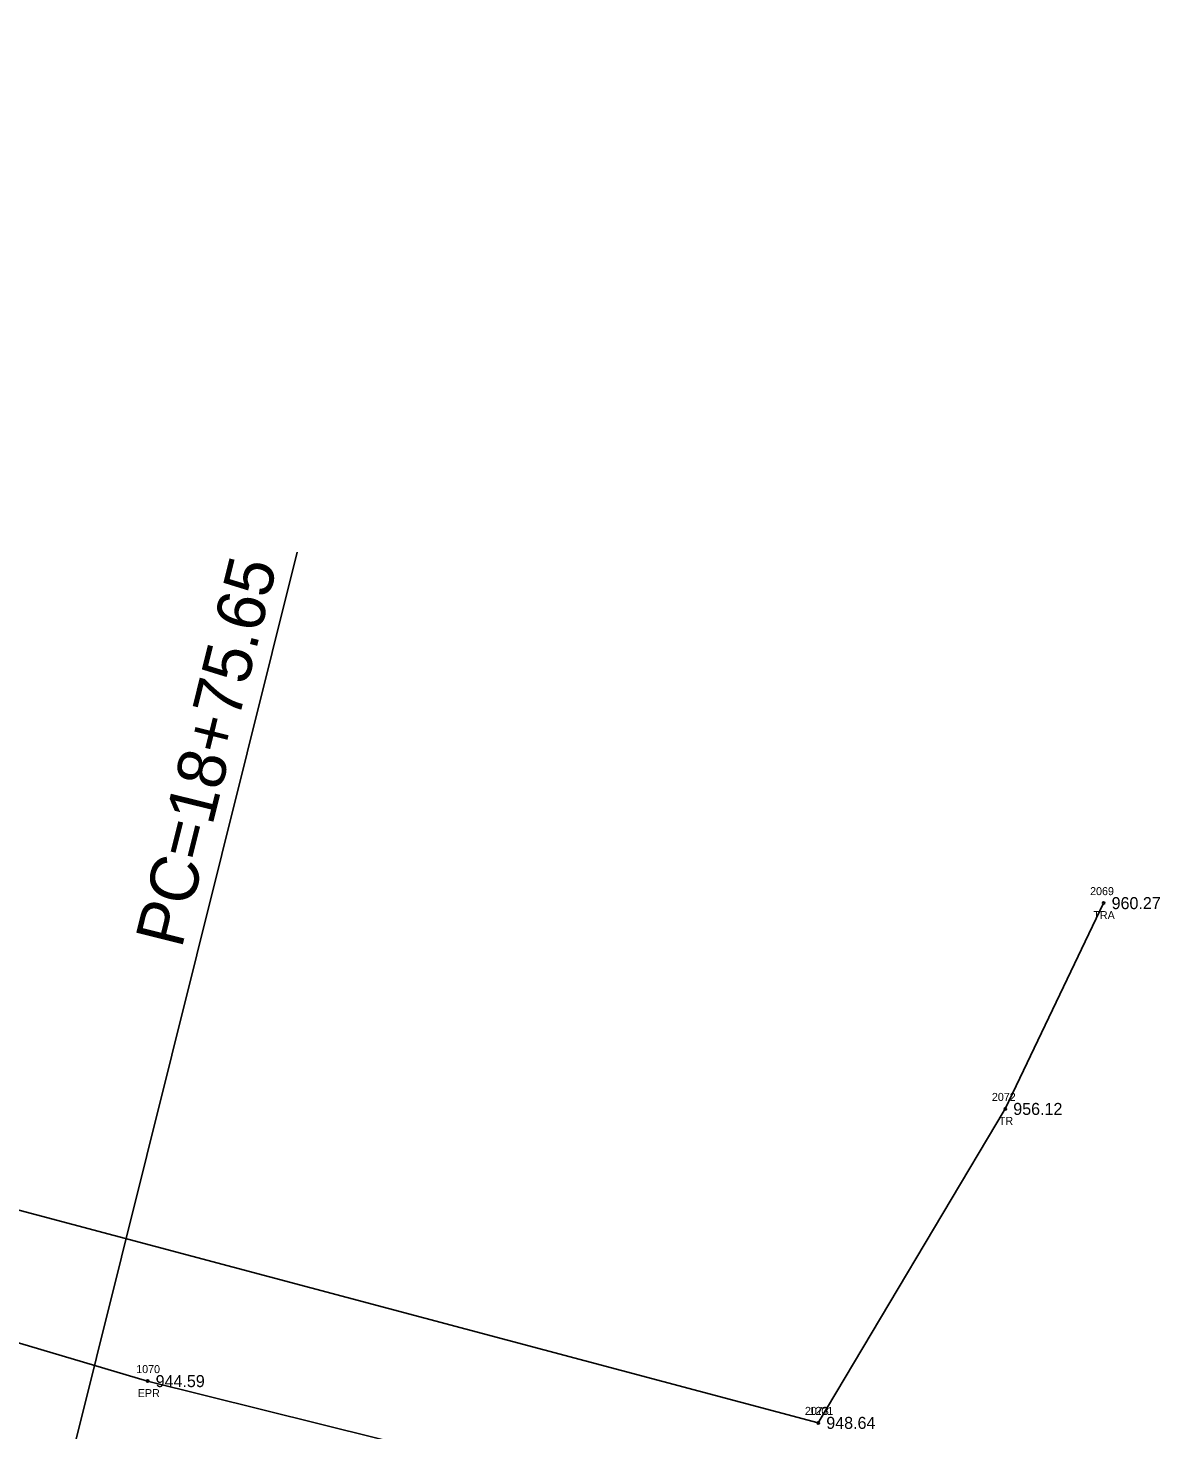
# Model space of a CAD drawing. Extents: x 1528109 to 1531398, y 1157799 to 1162548.
# Drawn here: x 1530236 to 1530377.4, y 1159171.6 to 1159346.8 of the extents above; entities that cross this region are included whole.
import ezdxf

# ---------------------------------------------------------------- set-up
doc = ezdxf.new("R2010")
doc.units = 0
for name, color, linetype in [('RD_EX_Road', 7, 'Continuous'), ('RD_EX_Road_txCode', 7, 'Continuous'), ('RD_EX_TX_Road_ELEV', 7, 'Continuous'), ('RD_EX_TX_VEG_ELEV', 7, 'Continuous'), ('RD_EX_VEG', 7, 'Continuous'), ('RD_EX_VEG_txCode', 7, 'Continuous'), ('RD_HC_Cl', 7, 'Continuous'), ('RD_HC_Data', 7, 'Continuous'), ('RD_SMD_Locator', 7, 'Continuous')]:
    doc.layers.add(name, color=color, linetype=linetype)

msp = doc.modelspace()

# ---------------------------------------------------------------- linework, layer by layer
at = {"layer": 'RD_EX_Road'}
msp.add_lwpolyline([(1530337.52, 1159156.44), (1530294.13, 1159166.93), (1530250.93, 1159177.7), (1530204.42, 1159191.5), (1530168.45, 1159204.97), (1530120.58, 1159231.54), (1530104.56, 1159243.15), (1530086.77, 1159257.61), (1530051.98, 1159290.88), (1530019.2, 1159326.18), (1529978.15, 1159378.31), (1529959.68, 1159408.2), (1529942.81, 1159442.34), (1529934.79, 1159460.88), (1529923.22, 1159491.09), (1529910.46, 1159527.95), (1529895.99, 1159570.93), (1529881.69, 1159613.98), (1529856.28, 1159690.67), (1529839.74, 1159739.71), (1529819.57, 1159800.04), (1529788.95, 1159890.99)], dxfattribs=at)
at = {"layer": 'RD_EX_VEG'}
for points in [[(1530334.72, 1159172.48), (1530202.71, 1159207.61), (1530119.87, 1159246.15), (1530082.28, 1159279.25), (1530129.08, 1159268.9), (1530183.31, 1159274.22)], [(1530370.37, 1159237.44), (1530358.08, 1159211.72), (1530334.72, 1159172.48)]]:
    msp.add_lwpolyline(points, dxfattribs=at)
at = {"layer": 'RD_HC_Cl'}
msp.add_arc((1530338.63, 1159558.58), 402.39, 222.8065, 256.0174, dxfattribs=at)
at = {"layer": 'RD_HC_Data'}
msp.add_line((1530241.41, 1159168.11), (1530269.59, 1159281.29), dxfattribs=at)
at = {"layer": 'RD_SMD_Locator'}
for centre in [(1530370.37, 1159237.44), (1530358.08, 1159211.72), (1530250.93, 1159177.7), (1530334.72, 1159172.48), (1530334.72, 1159172.48)]:
    msp.add_circle(centre, 0.15, dxfattribs=at)

# ---------------------------------------------------------------- texts
at = {"layer": 'RD_EX_Road_txCode'}
for s, p in [('1070', (1530249.5, 1159178.7)), ('EPR', (1530249.7, 1159175.7))]:
    msp.add_text(s, height=1, dxfattribs=at).set_placement(p)
at = {"layer": 'RD_EX_TX_Road_ELEV'}
msp.add_text('944.59', height=1.5, dxfattribs=at).set_placement((1530251.93, 1159176.95))
at = {"layer": 'RD_EX_TX_VEG_ELEV'}
for s, p in [('960.27', (1530371.37, 1159236.69)), ('956.12', (1530359.08, 1159210.97)), ('948.64', (1530335.72, 1159171.73)), ('948.64', (1530335.72, 1159171.73))]:
    msp.add_text(s, height=1.5, dxfattribs=at).set_placement(p)
at = {"layer": 'RD_EX_VEG_txCode'}
for s, p in [('2069', (1530368.68, 1159238.44)), ('TRA', (1530369.09, 1159235.44)), ('2072', (1530356.41, 1159212.72)), ('TR', (1530357.28, 1159209.72)), ('2073', (1530333.05, 1159173.48)), ('1201', (1530333.62, 1159173.48))]:
    msp.add_text(s, height=1, dxfattribs=at).set_placement(p)
at = {"layer": 'RD_HC_Data'}
msp.add_text('PC=18+75.65', height=6, rotation=76.0174, dxfattribs=at).set_placement((1530255.17, 1159231.66))

doc.saveas('drawing.dxf')
